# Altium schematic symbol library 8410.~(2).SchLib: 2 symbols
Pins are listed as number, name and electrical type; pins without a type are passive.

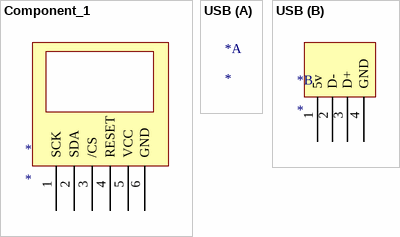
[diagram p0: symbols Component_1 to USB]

## Component_1
designator *
pins: 1 SCK, 2 SDA, 3 /CS, 4 RESET, 5 VCC, 6 GND

## USB
designator *
part B pins: 1 5v, 2 D-, 3 D+, 4 GND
